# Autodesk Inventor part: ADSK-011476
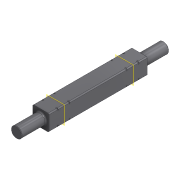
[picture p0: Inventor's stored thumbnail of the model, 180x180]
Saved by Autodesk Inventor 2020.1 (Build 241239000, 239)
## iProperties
Created: 1999-08
Part Number: ADSK-011476
Description: SHFTSP,FC,AX,010,135,022,022,SQ,TAIL,CONV
Material: Pearson CRS
Document SubType Name: Modeling
Designer: MP
Density: 7.83 g/cm^3
Appearance: Metal-Steel(Polish)
Mass: 3011.79 g
Surface Area: 453.444 cm^2
Volume: 384.648 cm^3
Control State: 0
Master: False
Checked Out: False
Shininess: 60.0
Length Units: 11269
Angle Units: 11279
Time Units: 11290
Mass Units: 11283
Length Display Precision: 3
Angle Display Precision: 2
Compacted: True
Cutlength: 13.5
Material Desc: FLAT,CRS,1.500X1.500
Material_Number: A084149
Dimensions: 38x343x38 mm
Mass: 3,012 kg
VLT_Material: Pearson CRS
Density: 7.83
Volumn: 387.64764002847664
Area: 455.0114274119862
PropertySet Name: Model Information
Author: MP
Revision Number: -
Title: SHFTSP,FC,AX,010,135,022,022,SQ,TAIL,CONV
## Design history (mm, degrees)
node "Extrusion1" dims "d6" = 229, "d7" = 0
  sketch "Sketch1"
    geometry: L1 (-16.857, -19)-(16.857, -19); L2 (19, -16.857)-(19, 16.857); L3 (16.857, 19)-(-16.857, 19); L4 (-19, 16.857)-(-19, -16.857); A1 r 25.4 centre (0, 0) between (-16.857, 19) and (-19, 16.857); A2 r 25.4 centre (0, 0) between (19, 16.857) and (16.857, 19); A3 r 25.4 centre (0, 0) between (-19, -16.857) and (-16.857, -19); A4 r 25.4 centre (0, 0) between (16.857, -19) and (19, -16.857); 1 further point
    constraints: 8 end point, 8 point on circle, 4 centre point, 4 parallel, 3 concentric, 1 coincident, 1 horizontal, 1 perpendicular
    dimensions: "d12" = 25.4 radius of A2; "d30" = 38 distance between parallel lines of L1 L3; "d31" = 38 distance between parallel lines of L4 L2 (= d30)
node "Extrusion2" dims "d9" = 57, "d10" = 0
  sketch "Sketch2"
    geometry: C1 r 12.5 at (0, 0)
    constraints: 1 centre point
    dimensions: "d8" = 25 diameter of C1
node "Mirror1"
workplane "Work Plane1"
node "Extrusion4" dims "d19" = 2.2, "d20" = 0
  sketch "Sketch3"
    geometry: L1 (-16.857, 19)-(16.857, 19) reference; L2 (-19, -16.857)-(-19, 16.857) reference; L3 (19, 16.857)-(19, -16.857) reference; L4 (16.857, -19)-(-16.857, -19) reference; C1 r 24 at (0, 0); 2 further points
    constraints: 2 coincident, 1 centre point, 3 other
    dimensions: "d18" = 48 diameter of C1
node "Mirror2"
node "Fillet1" dims "d21" = 3
node "Chamfer1" dims "d22" = 1, "d23" = 1, "d29" = 45 deg
workplane "Work Plane2"
node "Extrusion5" dims "d25" = 0, "d26" = 2.2
  sketch "Sketch4"
    geometry: L1 (-19.05, -16.801)-(-19.05, 16.801); L2 (19.05, 16.801)-(19.05, -16.801); L3 (16.801, -19.05)-(-16.801, -19.05); C1 r 25.4 at (0, 0); C2 r 24.13 at (0, 0); A1 r 25.4 centre (0, 0) between (19, 16.857) and (16.857, 19) reference; A2 r 25.4 centre (0, 0) between (19, 16.857) and (16.857, 19) reference; 1 further point
    constraints: 6 end point, 2 centre point, 2 coincident, 1 concentric
    dimensions: "d27" = 48.26 diameter of C2
workplane "Work Plane3"
node "Mirror3"
workplane "Arbeitsebene4"
workplane "Arbeitsebene5"
node "Solide1"
node "Corps solides"
node "Corps surfaciques"
node "Projizierte Kontur1"
other parameters: "d11" = 50.8, "d13" = 93.1164, "d14" = 48.26, "d24" = -48.768, "d28" = -114.3
